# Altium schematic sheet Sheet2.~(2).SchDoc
size A4; SheetNumber: 1; SheetTotal: 1
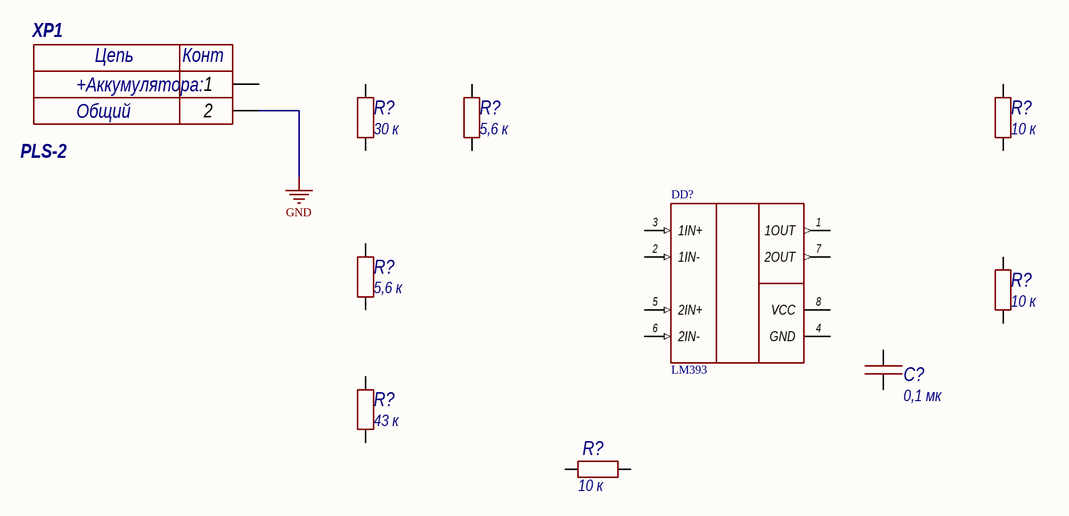
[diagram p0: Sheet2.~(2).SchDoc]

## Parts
(Parts that share a designator on the sheet are numbered #1, #2 ... from top to bottom, then left to right.)
C?  value 0,1 мк  [0603C]  (hidden comment: Capacitor)
DD?  LM393  [SOIC-8]
R?  value 10 к  [0603R]  (hidden comment: Resistor)
R?#1  value 30 к  [0603R]  (hidden comment: Resistor)
R?#2  value 5,6 к  [0603R]  (hidden comment: Resistor)
R?#3  value 10 к  [0603R]  (hidden comment: Resistor)
R?#4  value 5,6 к  [0603R]  (hidden comment: Resistor)
R?#5  value 10 к  [0603R]  (hidden comment: Resistor)
R?#6  value 43 к  [0603R]  (hidden comment: Resistor)
XP1  PLS-2  [PLS2]

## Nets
GND: XP1.2

Not connected (* = marked no-connect by the designer): C? 1 2; DD? 1(1OUT) 2(1IN-) 3(1IN+) 4(GND) 5(2IN+) 6(2IN-) 7(2OUT) 8(VCC); R? 1 2; R?#1 1 2; R?#2 1 2; R?#3 1 2; R?#4 1 2; R?#5 1 2; R?#6 1 2; XP1 1

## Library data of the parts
C? = Capacitor_0,1u_10_50V_X7R_0603C: Конденсатор 0603C ёмкостью 0,1 мк 10%, 50 В, X7R; Library Path2: Schematic\Capacitor.SchLib; Voltage (V): 50; Capacity (nF): 100
DD? = LM393: Двойной маломощный компаратор напряжения; MF: Texas Instruments; MP: LM393D
R? R?#3 R?#5 = Resistor_10k_1_0603: Резистор номиналом 10 кОм 1%
R?#1 = Resistor_30k_1_0603: Резистор номиналом 30 кОм 1%
R?#2 R?#4 = Resistor_5.6k_1_0603: Резистор номиналом 5,6 кОм 1%
R?#6 = Resistor_43k_1_0603: Резистор номиналом 43 кОм 1%
XP1 = PLS-2: Гребенка 2 пина; System: Connector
